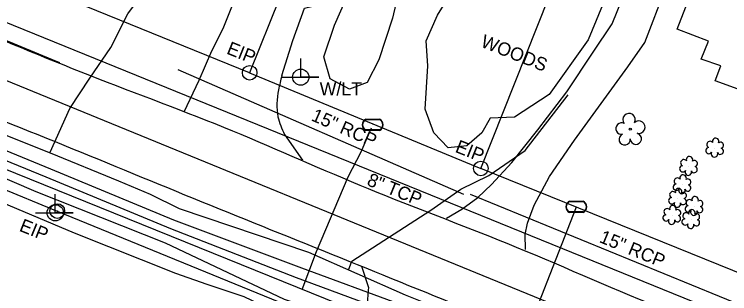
# Model space of a CAD drawing. Extents: x 2089016 to 2094354, y 862840 to 864725.
# Drawn here: x 2090207.9 to 2090423.3, y 864106.9 to 864191.1 of the extents above; entities that cross this region are included whole.
import ezdxf

# ---------------------------------------------------------------- set-up
doc = ezdxf.new("R2010")
doc.units = 0
for name, color, linetype in [('Exist Building', 7, 'Continuous'), ('Exist Horizontal Alignment', 7, 'Continuous'), ('Exist Property Iron Pin Text', 7, 'Continuous'), ('Exist Property Line', 7, 'Continuous'), ('Exist Right of Way Line', 7, 'Continuous'), ('Exist Roads EOP', 7, 'Continuous'), ('Exist Roads Soil', 7, 'Continuous'), ('Exist Structure Minor Pipes RCP 12 Inch', 7, 'Continuous'), ('Exist Structure Minor Pipes RCP 15 Inch', 7, 'Continuous'), ('Exist Structure Minor Pipes RCP 15 Inch Text', 7, 'Continuous'), ('Exist Utilities Gas UG Line SUE LOS B', 7, 'Continuous'), ('Exist Utilities Other Unknown UG SUE LOS B', 7, 'Continuous'), ('Exist Utilities Power Joint Use Telephone Text', 7, 'Continuous'), ('Exist Utilities Sanitary Sewer UG Line', 7, 'Continuous'), ('Exist Utilities Sanitary Sewer UG Line Text', 7, 'Continuous'), ('Exist Utilities Telephone UG Cable SUE LOS B', 7, 'Continuous'), ('Exist Utilities Telephone UG FO SUE LOS B', 7, 'Continuous'), ('Exist Utilities Water UG Line SUE LOS B', 7, 'Continuous'), ('Exist Utilities Water UG Line SUE LOS C', 7, 'Continuous'), ('Exist Vegetation Shrub CELL', 7, 'Continuous'), ('Exist Vegetation Tree CELL', 7, 'Continuous'), ('Exist Vegetation Woods Line', 7, 'Continuous'), ('Exist Vegetation Woods Line Text', 7, 'Continuous'), ('Pattern 1', 7, 'Continuous'), ('Prop Conc Curb and Gutter', 7, 'Continuous'), ('Prop SS Fill Line', 7, 'Continuous')]:
    doc.layers.add(name, color=color, linetype=linetype)

msp = doc.modelspace()

# ---------------------------------------------------------------- linework, layer by layer
at = {"layer": 'Exist Building'}
msp.add_lwpolyline([(2090419.55, 864217.79), (2090445.86, 864207.84), (2090446.4, 864208.24), (2090447.98, 864212.43), (2090452.61, 864215.35), (2090457.52, 864213.44), (2090458.9, 864208.16), (2090457.38, 864203.61), (2090458.79, 864203.14), (2090447.27, 864171.33), (2090437.05, 864175.29), (2090435.15, 864169.66), (2090428.39, 864172.47), (2090426.9, 864168.14), (2090418.88, 864171.04), (2090420.59, 864175.57), (2090414.67, 864177.54), (2090416.88, 864182.97), (2090407.44, 864186.65)], close=True, dxfattribs=at)
at = {"layer": 'Exist Horizontal Alignment'}
msp.add_line((2090185.23, 864179.42), (2091053.8, 863823.9), dxfattribs=at)
at = {"layer": 'Exist Property Line'}
for p, q in [((2090359.6, 864376.12), (2090278.77, 864173.48)), ((2090348.37, 864144.65), (2090428.89, 864347.42))]:
    msp.add_line(p, q, dxfattribs=at)
at = {"layer": 'Exist Right of Way Line'}
for p, q in [((2090278.77, 864173.48), (2090186.22, 864211.33)), ((2090109.5, 864177.3), (2090220.85, 864131.8)), ((2090278.77, 864173.48), (2090348.37, 864144.65)), ((2090463.85, 864097.83), (2090348.36, 864144.65)), ((2090220.85, 864131.8), (2090313.31, 864093.94))]:
    msp.add_line(p, q, dxfattribs=at)
at = {"layer": 'Exist Roads EOP'}
msp.add_lwpolyline([(2090189.67, 864189.72), (2090219.34, 864177.49), (2090221.53, 864176.58)], dxfattribs=at)
for points in [[(2090168.38, 864198.76), (2090189.5, 864189.72), (2090230.53, 864172.75), (2090273.59, 864155.99), (2090314.47, 864138.57), (2090356.17, 864122.11), (2090401.7, 864102.94), (2090442.19, 864087.09), (2090481.45, 864070.2), (2090523.64, 864052.97), (2090568.11, 864034.48), (2090610.4, 864017.13), (2090655.12, 863999.01), (2090697.83, 863981.77), (2090742.36, 863964.54), (2090779.16, 863949.36), (2090823.64, 863930.17), (2090867.73, 863911.82), (2090910.45, 863894.46), (2090950.82, 863877.93), (2090971.61, 863869.44), (2091006.7, 863856.03), (2091045.62, 863839.26), (2091086.07, 863822.83), (2091122.3, 863807.64), (2091162.46, 863791.02), (2091203.94, 863773.83), (2091243.88, 863757.78), (2091278.52, 863743.03), (2091290.86, 863741.47), (2091305.69, 863743.45)], [(2090159.86, 864177.45), (2090180.67, 864168.73), (2090222.86, 864151.65), (2090264.39, 864134.6), (2090306, 864117.79), (2090347.24, 864101.05), (2090392.99, 864082.57), (2090433.2, 864065.09), (2090472.83, 864048.96), (2090514.73, 864032.43), (2090559.97, 864014.05), (2090601.37, 863997.19), (2090646.29, 863978.82), (2090688.95, 863961.27), (2090733.38, 863942.96), (2090770.05, 863927.33), (2090814.52, 863908.72), (2090858.91, 863891), (2090901.15, 863874.17), (2090939.87, 863858.28), (2090962.72, 863848.64), (2090997.54, 863834.72), (2091036.07, 863819.08), (2091075.6, 863802.48), (2091112.88, 863787.77), (2091153.64, 863770.65), (2091194.67, 863753.49), (2091234.07, 863737.23), (2091276.57, 863719.33), (2091296.56, 863710.75), (2091332.88, 863695.67), (2091370.71, 863680.05), (2091411.45, 863662.85), (2091427.01, 863655.9), (2091440.19, 863646.8), (2091448.83, 863640.62), (2091463.67, 863633.85), (2091467.99, 863632.17), (2091469.11, 863631.07), (2091469.97, 863630.04), (2091470.37, 863629.28)]]:
    msp.add_spline(points, degree=3, dxfattribs=at)
at = {"layer": 'Exist Roads Soil'}
for p, q in [((2090387.95, 864188.19), (2090399.5, 864217.15)), ((2090289.27, 864154.88), (2090294.68, 864147.12)), ((2090314.61, 864108.67), (2090312.53, 864115.06))]:
    msp.add_line(p, q, dxfattribs=at)
for points in [[(2090288.46, 864172.68), (2090291.8, 864183.23), (2090295.26, 864192.99), (2090298.16, 864193.71), (2090302.17, 864194.53), (2090304.51, 864195.58), (2090306.46, 864198.02), (2090309.66, 864205.09), (2090317.37, 864226.64), (2090320.99, 864237.49), (2090325.4, 864235.87), (2090332.14, 864254.07), (2090339.14, 864272.14), (2090349.73, 864301.12)], [(2090267.41, 864180.05), (2090270.83, 864186.79), (2090275.83, 864199.47), (2090283.5, 864219.22), (2090291.02, 864238.13), (2090299.1, 864258.14), (2090301.71, 864265.32), (2090303.62, 864270.88), (2090304.54, 864275.18), (2090306.09, 864281.57), (2090306.64, 864286.11), (2090305.85, 864289.64), (2090303.96, 864292.21), (2090300.8, 864294.22), (2090296.32, 864296.09)], [(2090397.75, 864182.56), (2090410.41, 864215.63), (2090400.33, 864219.51), (2090399.5, 864217.15)], [(2090338.03, 864129.65), (2090342.66, 864132.32), (2090347.47, 864135.93), (2090351.58, 864139.83), (2090357.73, 864146.42), (2090365.53, 864156.29), (2090374.24, 864167.7), (2090382.14, 864179.73), (2090387.95, 864188.19)], [(2090361.77, 864120.17), (2090361.67, 864124.72), (2090362.42, 864128.13), (2090364.38, 864133.54), (2090369.02, 864142.2), (2090376.59, 864153.12), (2090392.59, 864175.29), (2090397.75, 864182.56)], [(2090259.05, 864161.76), (2090263.54, 864171.26), (2090267.41, 864180.05)]]:
    msp.add_lwpolyline(points, dxfattribs=at)
for points in [[(2090288.46, 864172.68), (2090287.47, 864168.3), (2090287.28, 864160.25), (2090289.27, 864154.88)], [(2090312.65, 864094.22), (2090313.08, 864097.81), (2090314.15, 864103.72), (2090314.61, 864108.67)]]:
    msp.add_spline(points, degree=3, dxfattribs=at)
at = {"layer": 'Exist Structure Minor Pipes RCP 12 Inch'}
msp.add_line((2090323.62, 864146.39), (2090323.62, 864146.39), dxfattribs=at)
at = {"layer": 'Exist Structure Minor Pipes RCP 15 Inch'}
for p, q in [((2090257.13, 864174.51), (2090343.13, 864136.92)), ((2090345.12, 864136.88), (2090438.81, 864098.43))]:
    msp.add_line(p, q, dxfattribs=at)
at = {"layer": 'Exist Utilities Gas UG Line SUE LOS B'}
for points in [[(2090218.73, 864149.54), (2090224.65, 864162.67), (2090230.7, 864171.86), (2090237.02, 864181.14), (2090242.1, 864191.26), (2090250.62, 864202.79)], [(2090164.72, 864171.24), (2090176.81, 864165.95), (2090183.84, 864163.19), (2090218.7, 864149.33), (2090239.31, 864140.91), (2090248.79, 864136.94), (2090257.5, 864132.61), (2090296.44, 864119.36), (2090325.61, 864106.59), (2090336.11, 864102.31), (2090341.15, 864100.26), (2090362.17, 864090.96), (2090387.11, 864080.57), (2090420.22, 864068.46), (2090434.6, 864061.74), (2090449.68, 864054.5), (2090471.08, 864044.88), (2090518.16, 864026.15), (2090555.56, 864011.22), (2090578.14, 864002.02), (2090597.24, 863994.69), (2090632.6, 863977.8)], [(2090308.56, 864113.98), (2090309.51, 864116.72), (2090333.29, 864132.07), (2090342.36, 864138.35), (2090350.8, 864142.48), (2090361.73, 864150.03), (2090374.68, 864166.88)]]:
    msp.add_lwpolyline(points, dxfattribs=at)
at = {"layer": 'Exist Utilities Other Unknown UG SUE LOS B'}
msp.add_lwpolyline([(2090160.74, 864160.6), (2090172.36, 864155.31), (2090179.54, 864152.69), (2090214.37, 864137.68), (2090253.35, 864122.24), (2090289.17, 864105.27), (2090319.9, 864094.9), (2090336.51, 864088.84), (2090356.77, 864080.84), (2090381.47, 864067.6), (2090410.48, 864050.36), (2090426.99, 864040.8), (2090437.84, 864034.14), (2090460.17, 864022.03), (2090475.87, 864015.05)], dxfattribs=at)
at = {"layer": 'Exist Utilities Sanitary Sewer UG Line'}
msp.add_lwpolyline([(2091692.13, 864500.83), (2091501.01, 864105.51), (2091469.71, 863953.2), (2091320.59, 863732.95), (2090957.27, 863880.97), (2090681.31, 863994.88), (2090015.26, 864266.1)], dxfattribs=at)
at = {"layer": 'Exist Utilities Telephone UG Cable SUE LOS B'}
msp.add_lwpolyline([(2090163.54, 864166.73), (2090174.81, 864162.5), (2090182.43, 864159.53), (2090218.82, 864144.49), (2090255.88, 864129.12), (2090294.4, 864114.66), (2090323.76, 864103.82), (2090340.8, 864097.42), (2090361.13, 864089.81), (2090385.93, 864079.24), (2090418.88, 864066.2), (2090433.4, 864059.75), (2090448.44, 864052.74), (2090470.62, 864043.8), (2090517.47, 864024.72), (2090548.17, 864012.66)], dxfattribs=at)
at = {"layer": 'Exist Utilities Telephone UG FO SUE LOS B'}
msp.add_lwpolyline([(2090162.35, 864164.53), (2090173.22, 864159.66), (2090181.27, 864156.88), (2090217.36, 864142.1), (2090254.94, 864126.56), (2090292.77, 864111.77), (2090321.74, 864101), (2090338.16, 864093.68), (2090359.72, 864086.31), (2090384.51, 864076.99), (2090408.07, 864065.93), (2090411.66, 864063.35), (2090416.51, 864060.98), (2090431.12, 864054.05), (2090446.07, 864047.9), (2090468.15, 864038.9), (2090516.86, 864022.7), (2090554.46, 864008.23), (2090596.02, 863991.07), (2090632.13, 863975.98)], dxfattribs=at)
at = {"layer": 'Exist Utilities Water UG Line SUE LOS B'}
msp.add_lwpolyline([(2090294.61, 864108.13), (2090298.85, 864119.57), (2090308.44, 864142.15), (2090312.31, 864149.69), (2090315.41, 864156.87)], dxfattribs=at)
at = {"layer": 'Exist Utilities Water UG Line SUE LOS C'}
msp.add_line((2090357.56, 864082.7), (2090377.13, 864133.08), dxfattribs=at)
msp.add_lwpolyline([(2090161.26, 864162.2), (2090526.87, 864014.14), (2090843.58, 863882.51)], dxfattribs=at)
at = {"layer": 'Exist Vegetation Shrub CELL'}
for p, q in [((2090418.84, 864150.75), (2090418.84, 864150.75)), ((2090410.97, 864145.23), (2090410.97, 864145.23)), ((2090409.03, 864139.69), (2090409.03, 864139.69)), ((2090407.66, 864135.59), (2090407.66, 864135.59)), ((2090412.64, 864133.17), (2090412.64, 864133.17)), ((2090405.94, 864130.44), (2090405.94, 864130.44)), ((2090411.66, 864129.2), (2090411.66, 864129.2))]:
    msp.add_line(p, q, dxfattribs=at)
for centre, radius, start, end in [((2090419.07, 864152.79), 0.99, 334.8391, 200.4717), ((2090417.04, 864150.04), 0.955, 95.1099, 327.9534), ((2090417.36, 864151.88), 0.968, 35.8908, 245.4216), ((2090420.52, 864151.62), 0.929, 284.4567, 126.0861), ((2090418.71, 864149.07), 0.984, 151.2797, 21.387), ((2090420.48, 864149.82), 0.937, 204.9913, 73.4601), ((2090409.48, 864146.36), 0.968, 35.8908, 245.4216), ((2090411.19, 864147.27), 0.99, 334.8391, 200.4717), ((2090412.64, 864146.1), 0.929, 284.4567, 126.0861), ((2090409.17, 864144.53), 0.955, 95.1099, 327.9534), ((2090412.6, 864144.3), 0.937, 204.9913, 73.4601), ((2090409.26, 864141.73), 0.99, 334.8391, 200.4717), ((2090410.84, 864143.55), 0.984, 151.2797, 21.387), ((2090407.55, 864140.82), 0.968, 35.8908, 245.4216), ((2090410.7, 864140.56), 0.929, 284.4567, 126.0861), ((2090407.23, 864138.99), 0.955, 95.1099, 327.9534), ((2090407.89, 864137.63), 0.99, 334.8391, 200.4717), ((2090408.9, 864138.01), 0.984, 151.2797, 21.387), ((2090410.67, 864138.76), 0.937, 204.9913, 73.4601), ((2090405.86, 864134.89), 0.955, 95.1099, 327.9534), ((2090406.18, 864136.72), 0.968, 35.8908, 245.4216), ((2090409.33, 864136.46), 0.929, 284.4567, 126.0861), ((2090412.87, 864135.21), 0.99, 334.8391, 200.4717), ((2090407.53, 864133.91), 0.984, 151.2797, 21.387), ((2090409.3, 864134.66), 0.937, 204.9913, 73.4601), ((2090411.16, 864134.29), 0.968, 35.8908, 245.4216), ((2090414.31, 864134.04), 0.929, 284.4567, 126.0861), ((2090404.46, 864131.57), 0.968, 35.8908, 245.4216), ((2090406.17, 864132.49), 0.99, 334.8391, 200.4717), ((2090407.62, 864131.31), 0.929, 284.4567, 126.0861), ((2090410.84, 864132.46), 0.955, 95.1099, 327.9534), ((2090411.89, 864131.24), 0.99, 334.8391, 200.4717), ((2090412.51, 864131.48), 0.984, 151.2797, 21.387), ((2090414.28, 864132.24), 0.937, 204.9913, 73.4601), ((2090404.14, 864129.74), 0.955, 95.1099, 327.9534), ((2090407.58, 864129.52), 0.937, 204.9913, 73.4601), ((2090409.86, 864128.5), 0.955, 95.1099, 327.9534), ((2090410.17, 864130.33), 0.968, 35.8908, 245.4216), ((2090413.33, 864130.07), 0.929, 284.4567, 126.0861), ((2090405.82, 864128.76), 0.984, 151.2797, 21.387), ((2090411.53, 864127.52), 0.984, 151.2797, 21.387), ((2090413.29, 864128.28), 0.937, 204.9913, 73.4601)]:
    msp.add_arc(centre, radius, start, end, dxfattribs=at)
at = {"layer": 'Exist Vegetation Tree CELL'}
msp.add_line((2090393.36, 864156.5), (2090393.36, 864156.5), dxfattribs=at)
msp.add_circle((2090393.36, 864156.5), 0.326, dxfattribs=at)
for centre, radius, start, end in [((2090392.97, 864159.37), 1.86, 330.1651, 219.7134), ((2090390.75, 864156.65), 1.73, 62.6636, 279.3457), ((2090395.91, 864157.08), 1.9, 257.1011, 134.1999), ((2090395.03, 864153.6), 1.7, 181.2822, 74.56), ((2090391.65, 864153.38), 1.69, 111.5671, 6.231)]:
    msp.add_arc(centre, radius, start, end, dxfattribs=at)
at = {"layer": 'Exist Vegetation Woods Line'}
for points in [[(2090324.42, 864213.15), (2090324.15, 864200.39), (2090321.79, 864189.9), (2090317.63, 864177.43), (2090314.16, 864170.59), (2090308.84, 864168.5), (2090303, 864171.65), (2090301.14, 864178.29), (2090304.34, 864187.88), (2090309.23, 864199.04), (2090314.29, 864212.77), (2090318.86, 864224.95), (2090321.55, 864226.66), (2090322.06, 864224), (2090321.15, 864218.36), (2090324.42, 864213.15)], [(2090387.92, 864225.65), (2090389.78, 864215.85), (2090386.16, 864196.89), (2090380.68, 864183.42), (2090368.95, 864166.89), (2090358.49, 864160.09), (2090351.14, 864159.81), (2090348.64, 864155.41), (2090344.15, 864151.42), (2090338.52, 864150.89), (2090334.26, 864155.38), (2090331.65, 864162.56), (2090332.42, 864175.6), (2090331.94, 864183.12), (2090335.37, 864190.86), (2090340.43, 864199.16), (2090346.57, 864200.93), (2090351.1, 864200.98), (2090355.83, 864198.22), (2090363.13, 864203.72), (2090370.27, 864210.34), (2090375.79, 864220.41), (2090378.48, 864226.77), (2090387.92, 864225.65)], [(2090170.26, 864152.53), (2090202, 864135.33), (2090225.96, 864125.25), (2090256.4, 864113.12), (2090265.88, 864109.76)], [(2090265.88, 864109.76), (2090277.02, 864106.04), (2090283.92, 864102.73), (2090289.41, 864096.31), (2090293.45, 864088.86), (2090292.26, 864081.15), (2090289.74, 864073.58), (2090286.62, 864064.64), (2090283.83, 864056.41), (2090284.42, 864052.36), (2090288.72, 864049.47), (2090288.2, 864045.44), (2090281.55, 864044.5), (2090270.19, 864047.55), (2090264.56, 864054), (2090261.19, 864063.55), (2090256.02, 864070.46), (2090252.43, 864075.27)]]:
    msp.add_lwpolyline(points, dxfattribs=at)
at = {"layer": 'Pattern 1'}
for p, q in [((2090315.81, 864157.82), (2090315.81, 864157.82)), ((2090377.13, 864133.08), (2090377.13, 864133.08))]:
    msp.add_line(p, q, dxfattribs=at)
for points in [[(2090313.78, 864159.52), (2090317.85, 864159.52)], [(2090313.78, 864159.38), (2090317.85, 864159.38)], [(2090317.85, 864156.25), (2090313.75, 864156.25)], [(2090317.85, 864156.12), (2090313.75, 864156.12)], [(2090375.09, 864134.78), (2090379.16, 864134.78)], [(2090375.09, 864134.64), (2090379.16, 864134.64)], [(2090379.16, 864131.52), (2090375.06, 864131.52)], [(2090379.16, 864131.38), (2090375.06, 864131.38)]]:
    msp.add_lwpolyline(points, dxfattribs=at)
for centre, radius, start, end in [((2090314.51, 864157.81), 1.86, 113.178, 245.9794), ((2090317.11, 864157.82), 1.86, 293.6483, 66.3084), ((2090314.52, 864157.81), 1.73, 115.3009, 243.7824), ((2090317.12, 864157.82), 1.73, 295.1272, 64.8728), ((2090375.82, 864133.08), 1.86, 113.178, 245.9794), ((2090375.83, 864133.08), 1.73, 115.3009, 243.7824), ((2090378.42, 864133.08), 1.86, 293.6483, 66.3084), ((2090378.43, 864133.08), 1.73, 295.1272, 64.8728)]:
    msp.add_arc(centre, radius, start, end, dxfattribs=at)
at = {"layer": 'Prop Conc Curb and Gutter'}
for centre, radius in [((2090278.77, 864173.48), 2.2), ((2090278.77, 864173.48), 0.0707), ((2090348.37, 864144.65), 2.2), ((2090348.37, 864144.65), 0.0707), ((2090220.85, 864131.8), 2.2), ((2090220.85, 864131.8), 0.0707)]:
    msp.add_circle(centre, radius, dxfattribs=at)
at = {"layer": 'Prop SS Fill Line'}
for p, q in [((2090294.16, 864172.16), (2090294.16, 864172.16)), ((2090220.25, 864131.26), (2090220.25, 864131.26))]:
    msp.add_line(p, q, dxfattribs=at)
for points in [[(2090288.22, 864172.16), (2090299.56, 864172.12), (2090294.16, 864172.14), (2090294.16, 864177.78)], [(2090214.31, 864131.26), (2090225.65, 864131.22), (2090220.25, 864131.24), (2090220.25, 864136.89)]]:
    msp.add_lwpolyline(points, dxfattribs=at)
for centre in [(2090294.16, 864172.16), (2090220.25, 864131.27)]:
    msp.add_circle(centre, 2.45, dxfattribs=at)

# ---------------------------------------------------------------- texts
at = {"layer": 'Exist Property Iron Pin Text'}
for rotation, p in [(338.1965, (2090271.57, 864179.32)), (338.1965, (2090340.37, 864149.68)), (338.0261, (2090209.14, 864125.91))]:
    msp.add_text('EIP', height=4, rotation=rotation, dxfattribs=at).set_placement(p)
at = {"layer": 'Exist Structure Minor Pipes RCP 15 Inch Text'}
for rotation, p in [(336.3835, (2090297.03, 864159.21)), (337.6862, (2090383.75, 864122.51))]:
    msp.add_text('15" RCP', height=4, rotation=rotation, dxfattribs=at).set_placement(p)
at = {"layer": 'Exist Utilities Power Joint Use Telephone Text'}
msp.add_text('W/LT', height=4, dxfattribs=at).set_placement((2090299.84, 864166.65))
at = {"layer": 'Exist Utilities Sanitary Sewer UG Line Text'}
msp.add_text('8" TCP', height=4, rotation=337.8441, dxfattribs=at).set_placement((2090313.79, 864139.71))
at = {"layer": 'Exist Vegetation Woods Line Text'}
msp.add_text('WOODS', height=4, rotation=338.361, dxfattribs=at).set_placement((2090348.05, 864181.41))

doc.saveas('drawing.dxf')
